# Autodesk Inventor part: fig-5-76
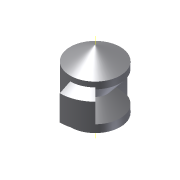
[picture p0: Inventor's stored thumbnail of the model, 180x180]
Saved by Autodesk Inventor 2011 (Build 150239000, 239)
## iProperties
Created: 2004-05
Part Number: fig-5-76
Document SubType Name: Modeling
Designer: CADCIM Technologies
Manufacturer: Standard
Standards Organization: Custom
Density: 1 g/cm^3
Author: CADCIM Technologies
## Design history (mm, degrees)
sketch "Sketch1"
  geometry: L1 (0, -21.51)-(0, 21.51); L2 (0, 21.51)-(-14.639, 13.059); L3 (-14.639, 13.059)-(-14.639, -13.059); L4 (-14.639, -13.059)-(0, -21.51); 2 further points
  constraints: 8 end point, 1 coincident, 1 equal length, 1 midpoint, 1 parallel, 1 vertical, 1 other
  dimensions: "d3" = 120 deg angle of L4 L3
revolve "Revolution1" sketch "Sketch1" stored, may be unused: angle "d0" = 90 deg
workaxis "Work Axis1"
sketch "Sketch2"
  geometry: L1 (-15.658, 10.423)-(-7.144, 0); L2 (-7.144, 0)-(-15.658, -9.738); L3 (-15.658, -9.738)-(-15.658, 10.423); L4 (0, -25.812)-(0, 34.416) reference
  constraints: 6 end point, 1 vertical
revolve "Revolution2" sketch "Sketch2" stored, may be unused: angle "d4" = 140 deg
sketch "Sketch3"
  geometry: L1 (-14.955, 9.983)-(-20.736, 7.191); L2 (-20.736, 7.191)-(-20.736, -7.686); L3 (-20.736, -7.686)-(-15, -10.57); L4 (0, -25.812)-(0, 34.416) reference
  constraints: 6 end point, 1 equal length, 1 vertical
revolve "Revolution4" sketch "Sketch3" stored, may be unused: angle "d9" = 45 deg
body "Solid1"
other parameters: "d10" = 45 deg
